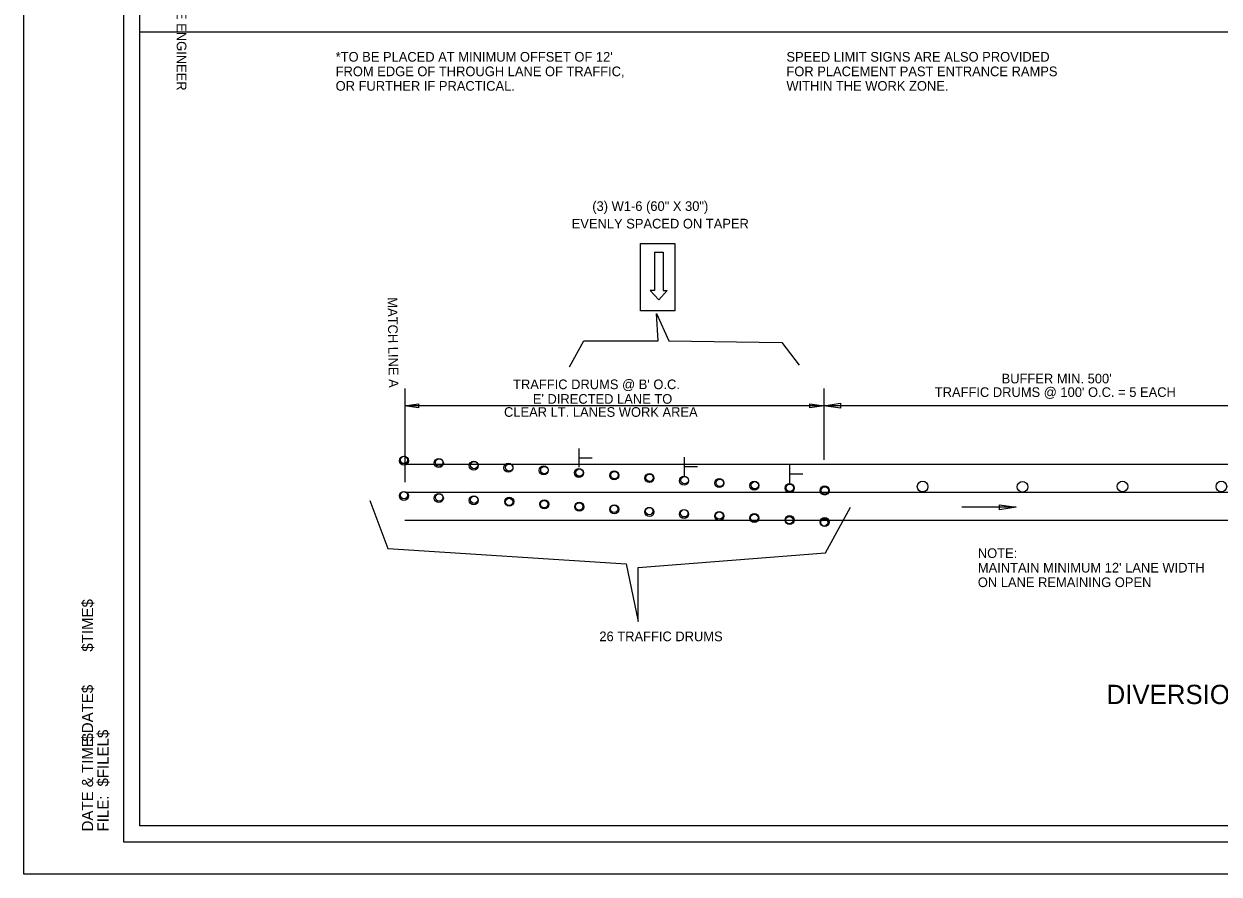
# Model space of a CAD drawing. Extents: x 13528 to 25043, y 7635 to 10612.
# Drawn here: x 15554 to 16297, y 9545 to 10073 of the extents above; entities that cross this region are included whole.
import ezdxf

# ---------------------------------------------------------------- set-up
doc = ezdxf.new("R2010")
doc.units = 0
for name, color, linetype in [('Default', 7, 'Continuous'), ('R_Border Notes', 7, 'Continuous'), ('R_Draft', 7, 'Continuous'), ('R_Revision Date Text', 7, 'Continuous')]:
    doc.layers.add(name, color=color, linetype=linetype)

msp = doc.modelspace()

# ---------------------------------------------------------------- linework, layer by layer
at = {"layer": 'Default'}
for p, q in [((15945.87, 9931.6), (15945.87, 9907.7)), ((15945.87, 9931.6), (15951.19, 9931.6)), ((15951.19, 9931.6), (15951.19, 9907.7)), ((15945.87, 9907.7), (15943.21, 9907.7)), ((15943.21, 9907.7), (15948.53, 9901.86)), ((15948.53, 9901.86), (15953.85, 9907.7)), ((15951.19, 9907.7), (15953.85, 9907.7)), ((15790.66, 9846.79), (15790.66, 9788.5)), ((16051.25, 9846.79), (16051.25, 9802.5)), ((15790.47, 9836), (15799.16, 9837.3)), ((16051.25, 9836), (15790.47, 9836)), ((15799.16, 9834.7), (15790.47, 9836)), ((15790.66, 9831.56), (15790.66, 9788.5)), ((15799.16, 9837.3), (15799.16, 9834.7)), ((16042.55, 9834.7), (16042.55, 9837.3)), ((16042.55, 9837.3), (16051.25, 9836)), ((16051.25, 9836), (16042.55, 9834.7)), ((16051.25, 9836), (16061.55, 9837.55)), ((16360.35, 9836), (16051.25, 9836)), ((16061.55, 9834.45), (16051.25, 9836)), ((16061.55, 9837.55), (16061.55, 9834.45)), ((15899.06, 9797.93), (15899.06, 9809.54)), ((15899.23, 9803.7), (15907.16, 9803.7)), ((15964.48, 9792.51), (15964.48, 9804.12)), ((15790.66, 9799.63), (16059.71, 9799.63)), ((15964.65, 9798.29), (15972.57, 9798.29)), ((16030.04, 9788), (16030.04, 9799.61)), ((16051.44, 9799.63), (16320.37, 9799.63)), ((16030.21, 9793.77), (16038.14, 9793.77)), ((15790.66, 9782.24), (16063.48, 9782.24)), ((16050.54, 9782.24), (16322.55, 9782.24)), ((16170.73, 9772.91), (16136.94, 9772.91)), ((16160.43, 9771.37), (16160.43, 9774.46)), ((16160.43, 9774.46), (16170.73, 9772.91)), ((16170.73, 9772.91), (16160.43, 9771.37)), ((15790.66, 9764.86), (16066.9, 9764.86)), ((16051.03, 9764.86), (16326.09, 9764.86))]:
    msp.add_line(p, q, dxfattribs=at)
msp.add_lwpolyline([(15937.11, 9895.03), (15937.11, 9936.94), (15958.55, 9936.94), (15958.55, 9895.03)], close=True, dxfattribs=at)
for points in [[(15893.02, 9860.17), (15902.02, 9876.47), (15948.25, 9876.47), (15947.05, 9893.36), (15954.86, 9876.47), (16025.11, 9875.31), (16035.91, 9861.34)], [(15768.86, 9777.13), (15780.14, 9747.22), (15928.24, 9737.73), (15935.75, 9701.99), (15935.75, 9735.54), (16052.24, 9744.58), (16067.78, 9772.91)]]:
    msp.add_lwpolyline(points, dxfattribs=at)
for centre, radius in [((15790.08, 9801.88), 2.81), ((15790.08, 9802.34), 2.29), ((15790.2, 9802.33), 2.29), ((15811.81, 9800.36), 2.81), ((15812.01, 9800.75), 2.29), ((15833.54, 9798.83), 2.81), ((15833.82, 9799.18), 2.29), ((15855.02, 9797.47), 2.81), ((15855.62, 9797.6), 2.29), ((15876.96, 9795.87), 2.81), ((15877.43, 9796.03), 2.29), ((15898.9, 9794.28), 2.81), ((15899.24, 9794.45), 2.29), ((15920.84, 9792.69), 2.81), ((15921.04, 9792.88), 2.29), ((15942.78, 9791.1), 2.81), ((15942.85, 9791.3), 2.29), ((15964.27, 9789.44), 2.81), ((15964.66, 9789.72), 2.29), ((15986.14, 9787.92), 2.81), ((15986.46, 9788.15), 2.29), ((16008.01, 9786.4), 2.81), ((16008.27, 9786.57), 2.29), ((16029.88, 9784.87), 2.81), ((16030.08, 9785), 2.29), ((16112.6, 9785.77), 3.33), ((16174.74, 9785.63), 3.33), ((16236.88, 9785.84), 3.33), ((16298.36, 9785.85), 3.33), ((15790.08, 9780), 2.81), ((15790.08, 9780.45), 2.29), ((15790.2, 9780.44), 2.29), ((15811.81, 9778.61), 2.81), ((15811.98, 9779.03), 2.29), ((15833.54, 9777.22), 2.81), ((15833.76, 9777.62), 2.29), ((15855.58, 9776.41), 2.81), ((16051.75, 9783.35), 2.81), ((16051.76, 9783.43), 2.29), ((16051.88, 9783.42), 2.29), ((15855.54, 9776.21), 2.29), ((15877.38, 9774.82), 2.81), ((15877.31, 9774.8), 2.29), ((15899.18, 9773.23), 2.81), ((15899.09, 9773.39), 2.29), ((15920.98, 9771.63), 2.81), ((15920.87, 9771.98), 2.29), ((15942.78, 9770.04), 2.81), ((15942.65, 9770.57), 2.29), ((15964.27, 9768.67), 2.81), ((15964.43, 9769.16), 2.29), ((15986.14, 9767.42), 2.81), ((15986.21, 9767.75), 2.29), ((16008.01, 9766.17), 2.81), ((16007.98, 9766.34), 2.29), ((16029.88, 9764.93), 2.81), ((16029.76, 9764.93), 2.29), ((16051.75, 9763.68), 2.81), ((16051.42, 9763.53), 2.29), ((16051.54, 9763.52), 2.29)]:
    msp.add_circle(centre, radius, dxfattribs=at)
at = {"layer": 'R_Draft'}
for p, q in [((15615.87, 9564.77), (15615.87, 10592.07)), ((15615.87, 9564.77), (15615.87, 9564.77)), ((17196.77, 9564.77), (15615.87, 9564.77))]:
    msp.add_line(p, q, dxfattribs=at)
at = {"layer": 'R_Revision Date Text'}
for points in [[(15553.84, 10611.55), (17220.54, 10611.55), (17220.54, 9544.86), (15553.84, 9544.86)], [(15625.87, 10582.07), (16873.57, 10582.07), (16873.57, 10532.67), (16961.27, 10532.67), (17081.77, 10532.67), (17081.77, 10421.01), (17186.77, 10421.01), (17186.77, 9574.77), (15625.87, 9574.77)], [(15625.87, 10068.42), (17186.77, 10068.42), (17186.77, 9574.77), (15625.87, 9574.77)]]:
    msp.add_lwpolyline(points, close=True, dxfattribs=at)

# ---------------------------------------------------------------- texts
at = {"layer": 'Default'}
for s, rotation, p in [('TO BE USED IF AND WHERE DIRECTED BY THE ENGINEER', 270, (15648.87, 10259.74)), ("*TO BE PLACED AT MINIMUM OFFSET OF 12'", 360, (15747.66, 10049.97)), ('FROM EDGE OF THROUGH LANE OF TRAFFIC,', 360, (15747.66, 10040.92)), ('OR FURTHER IF PRACTICAL.', 360, (15747.66, 10031.88)), ('(3) W1-6 (60" X 30")', 0.00754, (15907.21, 9957.14)), ('EVENLY SPACED ON TAPER', 0.00754, (15894.43, 9946.23)), ('MATCH LINE A', 270.80593, (15779.97, 9903.4))]:
    msp.add_text(s, height=6, rotation=rotation, dxfattribs=at).set_placement(p)
for s, height, p in [('SPEED LIMIT SIGNS ARE ALSO PROVIDED', 6, (16027.93, 10049.97)), ('FOR PLACEMENT PAST ENTRANCE RAMPS ', 6, (16027.93, 10040.92)), ('WITHIN THE WORK ZONE.', 6, (16027.93, 10031.88)), ("BUFFER MIN. 500'", 6, (16161.72, 9849.93)), ("TRAFFIC DRUMS @ B' O.C.", 6, (15857.98, 9846.34)), ("TRAFFIC DRUMS @ 100' O.C. = 5 EACH", 6, (16120.17, 9841.5)), ("E' DIRECTED LANE TO", 6, (15870.26, 9837.27)), ('CLEAR LT. LANES WORK AREA', 6, (15852.35, 9829.14)), ('NOTE:', 6, (16146.94, 9741.4)), ("MAINTAIN MINIMUM 12' LANE WIDTH", 6, (16146.94, 9732.35)), ('ON LANE REMAINING OPEN', 6, (16146.94, 9723.3)), ('26 TRAFFIC DRUMS', 6, (15911.61, 9689.65)), ('DIVERSION FOR LT. LANE WORK ZONE', 12, (16226.98, 9650.56))]:
    msp.add_text(s, height=height, dxfattribs=at).set_placement(p)
at = {"layer": 'R_Border Notes'}
for s, height, p in [('$TIME$', 6.984, (15596.87, 9683.12)), ('$DATE$', 6.984, (15596.87, 9627.25)), ('DATE & TIME:', 6.9839, (15596.87, 9571.38)), ('$FILEL$', 6.984, (15606.47, 9599.32)), ('FILE: ', 6.984, (15606.47, 9571.38))]:
    msp.add_text(s, height=height, rotation=90, dxfattribs=at).set_placement(p)

doc.saveas('drawing.dxf')
